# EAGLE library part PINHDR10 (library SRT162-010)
pinheader/pinsocket 1x10
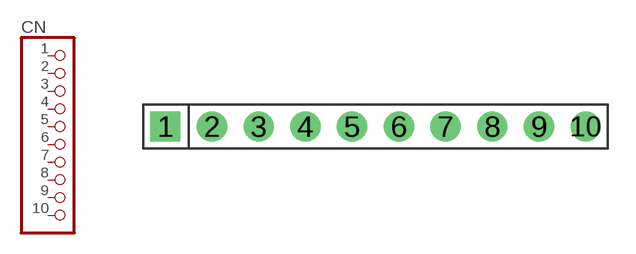
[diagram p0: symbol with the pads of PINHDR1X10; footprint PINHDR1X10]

Designator prefix CN

## PINHDR10  [PINHDR1X10]
1  1  pas
2  2  pas
3  3  pas
4  4  pas
5  5  pas
6  6  pas
7  7  pas
8  8  pas
9  9  pas
10  10  pas

## Footprint PINHDR1X10 (pad centres in mm)
drill 1.1 square: 1 -11.43,0
drill 1.1 round: 2 -8.89,0; 3 -6.35,0; 4 -3.81,0; 5 -1.27,0; 6 1.27,0; 7 3.81,0; 8 6.35,0; 9 8.89,0; 10 11.43,0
